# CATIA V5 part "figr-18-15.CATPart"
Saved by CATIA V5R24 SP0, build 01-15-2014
Part number: Part2
Bounding box of the stored display mesh (mm): x -49.377 to 49.377, y -53.665 to 53.665, z 0 to 34
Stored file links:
  D:\KAVITA\CATIA V5-6R2014 Project_ Kavita\CATIA V5-6R2014_partfiles\Partfiles\c17_caia_v6-6r2014_prt\fihr-17-15.CATPart
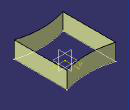
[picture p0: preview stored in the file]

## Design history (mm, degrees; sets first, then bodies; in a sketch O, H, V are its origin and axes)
Body1 (main body)
  Sketch1 on xy-plane, origin (0, 0, 0), H (1, 0, 0), V (0, 1, 0)
    spline S1 through (-49.3771, 53.665) (-5.7754, 46.0634) (49.3771, 53.665)
    line L1 (49.3771, 53.665) -> (49.3771, -53.665)
    point P1 (49.3771, 53.665)
    point P2 (49.3771, -53.665)
    spline S2 through (-49.3771, -53.665) (-5.7754, -46.0634) (49.3771, -53.665)
    point P3 (-49.3771, -53.665)
    point P4 (-49.3771, 53.665)
    line L2 (-49.3771, 53.665) -> (-49.3771, -53.665)
    point P5 (49.3771, 53.665)
    point P6 (49.3771, -53.665)
    point P7 (-49.3771, 53.665)
    point P8 (-49.3771, -53.665)
    point P9 (-5.7754, 46.0634)
    point P10 (-5.7754, -46.0634)
    coincidence: P5 P1, P6 P2, P8 P3
    vertical: L1 V
    symmetry: S1 S2 H, P5 P6 H, P7 P8 H, P9 P10 H, P2 P3 V, P1 P4 V, L1 L2 V
  Extrude1: Element1 Sketch1, Lim1 34, Lim2 0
